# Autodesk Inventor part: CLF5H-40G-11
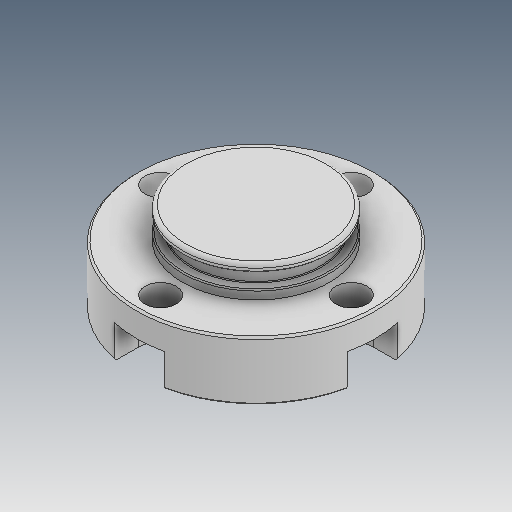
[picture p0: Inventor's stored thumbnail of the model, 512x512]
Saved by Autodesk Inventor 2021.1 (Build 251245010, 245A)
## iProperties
Created: 2013-04
Part Number: CLF5H-40G-11
Material: Ogólny
Document SubType Name: Modeling
Designer: user
Density: 1 g/cm^3
Appearance: Domyślna
Author: user
Revision Number: ÈÎºÎ
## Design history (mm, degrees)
feature "ÕóÁÐ(Ô²ÖÜ)1"
node "Bryła1"
